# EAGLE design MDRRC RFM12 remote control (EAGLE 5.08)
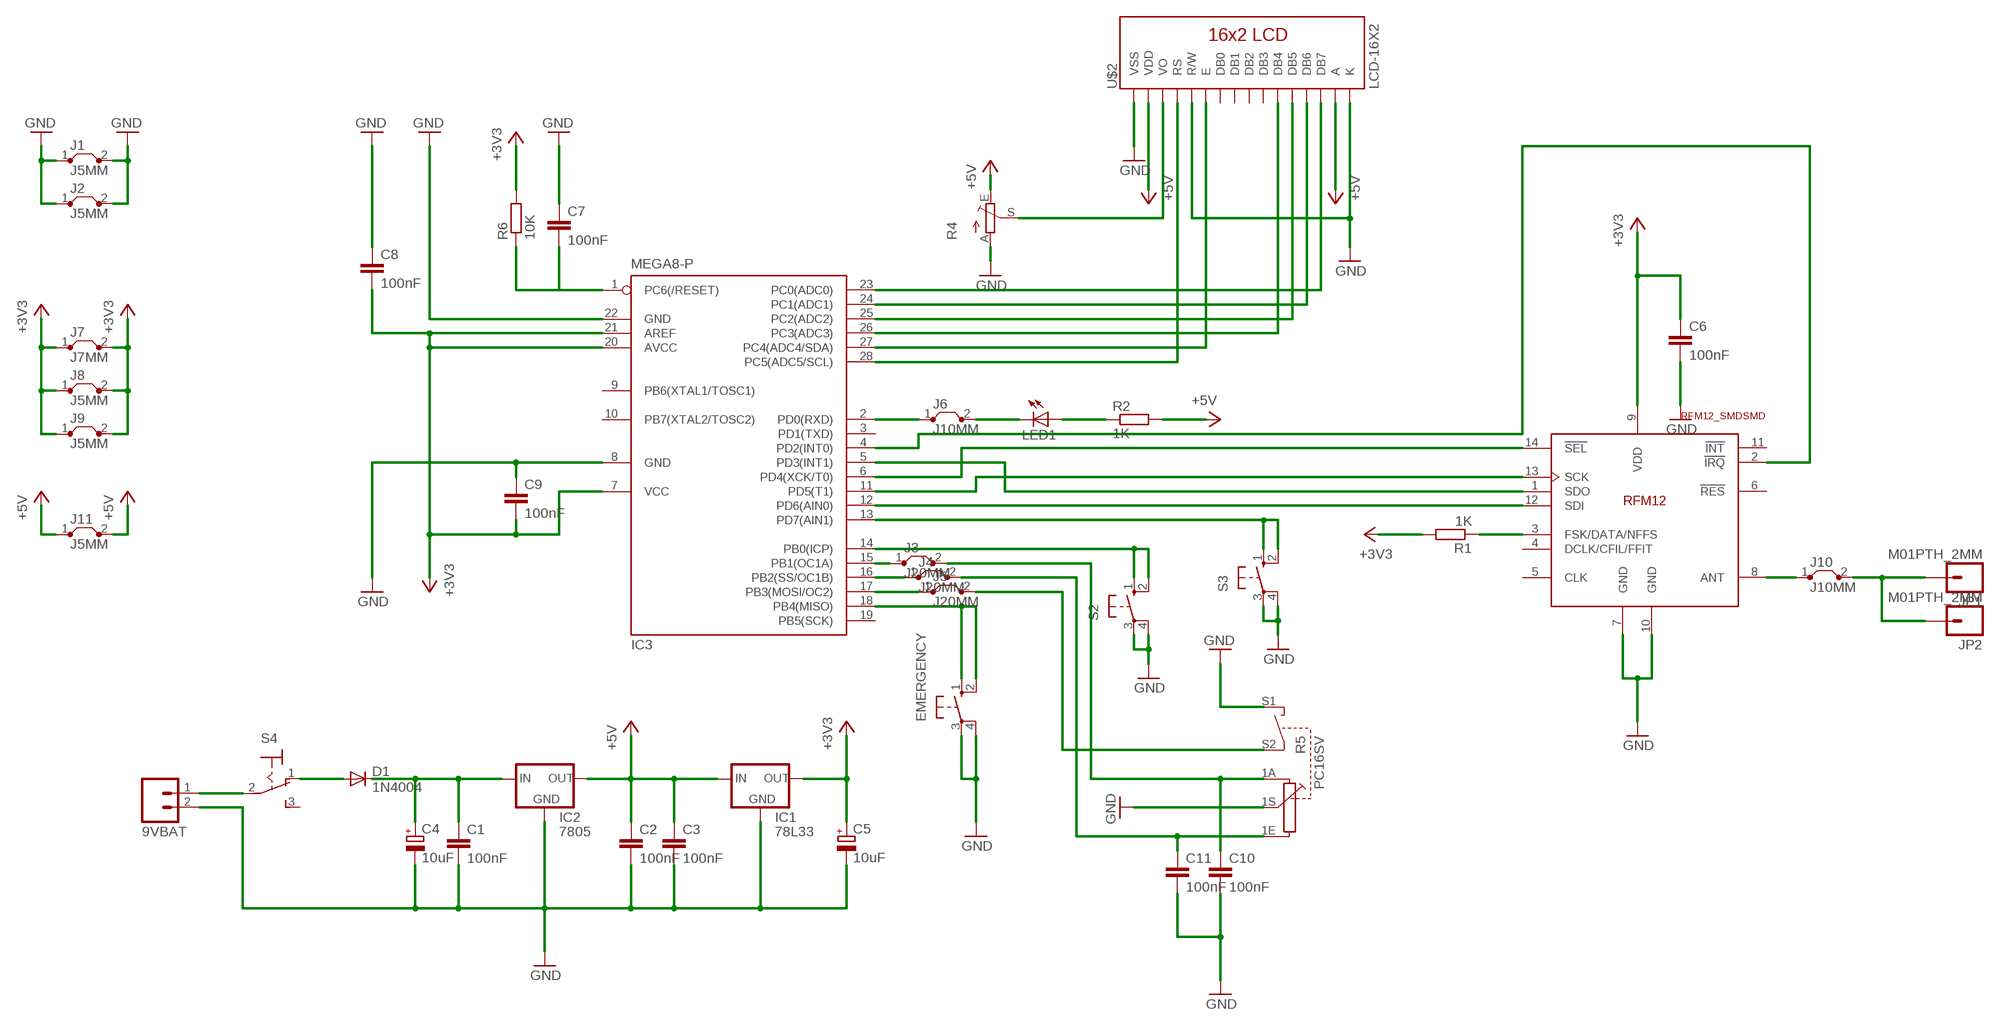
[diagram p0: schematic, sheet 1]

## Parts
9VBAT  M02LOCK_LONGPADS  [1X02_LOCK_LONGPADS]
C1  100nF  C-EU025-025X050  [C025-025X050]
C2  100nF  C-EU025-025X050  [C025-025X050]
C3  100nF  C-EU025-025X050  [C025-025X050]
C4  10uF  CPOL-EUE2.5-6  [E2,5-6]
C5  10uF  CPOL-EUE2.5-6  [E2,5-6]
C6  100nF  C-EU025-025X050  [C025-025X050]
C7  100nF  C-EU025-025X050  [C025-025X050]
C8  100nF  C-EU025-025X050  [C025-025X050]
C9  100nF  C-EU025-025X050  [C025-025X050]
C10  100nF  C-EU025-025X050  [C025-025X050]
C11  100nF  C-EU025-025X050  [C025-025X050]
D1  1N4004  [DO41-10]
EMERGENCY  10-XX  [B3F-10XX]
IC1  78L33  78LXX  [78LXX]
IC2  7805  78XXS  [78XXS]
IC3  MEGA8-P  [DIL28-3]
J1  J5MM  [05]
J2  J5MM  [05]
J3  J20MM  [20]
J4  J20MM  [20]
J5  J20MM  [20]
J6  J10MM  [10]
J7  J7MM  [07]
J8  J5MM  [05]
J9  J5MM  [05]
J10  J10MM  [10]
J11  J5MM  [05]
JP1  M01PTH_2MM  [1X01_2MM]
JP2  M01PTH_2MM  [1X01_2MM]
LED1  LED3MM  [LED3MM]
R1  1K  R-EU_0207/15  [0207/15]
R2  1K  R-EU_0207/10  [0207/10]
R4  TRIM_EU-CA6V  [CA6V]
R5  PC16SV  [PC16SV]
R6  10K  R-EU_0207/15  [0207/15]
S2  10-XX  [B3F-10XX]
S3  10-XX  [B3F-10XX]
S4  M9040P  [M9040P]
U$1  RFM12_SMDSMD  [RFM12]
U$2  LCD-16X2  [LCD-16X2]

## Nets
+3V3: C5.+ C6.1 C8.2 C9.2 IC1.OUT IC3.7(VCC) IC3.20(AVCC) IC3.21(AREF) J7.1 J7.2 J8.1 J8.2 J9.1 J9.2 R1.2 R6.2 U$1.9(VDD)
+5V: C2.1 C3.1 IC1.IN IC2.OUT J11.1 J11.2 R2.2 R4.E U$2.2(VDD) U$2.15(A)
GND: 9VBAT.2 C1.2 C2.2 C3.2 C4.- C5.- C6.2 C7.1 C8.1 C9.1 C10.2 C11.2 EMERGENCY.3(P) EMERGENCY.4(P1) IC1.GND IC2.GND IC3.8(GND) IC3.22(GND) J1.1 J1.2 J2.1 J2.2 R4.A R5.1S R5.S1 S2.3(P) S2.4(P1) S3.3(P) S3.4(P1) U$1.7(GND) U$1.10(GND) U$2.1(VSS) U$2.5(R/W) U$2.16(K)
N$1: D1.A S4.1(O)
N$2: C1.1 C4.+ D1.C IC2.IN
N$3: 9VBAT.1 S4.2(P)
N$4: IC3.2(PD0(RXD)) J6.1
N$5: C7.2 IC3.1(PC6(/RESET)) R6.1
N$6: R4.S U$2.3(VO)
N$7: J5.2 R5.S2
N$8: LED1.A R2.1
N$9: J6.2 LED1.K(C)
N$10: J10.2 JP1.1 JP2.1
N$11: R1.1 U$1.3(FSK/DATA/NFFS)
N$12: IC3.28(PC5(ADC5/SCL)) U$2.4(RS)
N$13: IC3.27(PC4(ADC4/SDA)) U$2.6(E)
N$14: IC3.23(PC0(ADC0)) U$2.14(DB7)
N$15: IC3.24(PC1(ADC1)) U$2.13(DB6)
N$16: IC3.25(PC2(ADC2)) U$2.12(DB5)
N$17: IC3.26(PC3(ADC3)) U$2.11(DB4)
N$18: IC3.12(PD6(AIN0)) U$1.12(SDI)
N$19: IC3.5(PD3(INT1)) U$1.1(SDO)
N$20: IC3.11(PD5(T1)) U$1.13(SCK)
N$21: IC3.6(PD4(XCK/T0)) U$1.14(!SEL)
N$22: IC3.4(PD2(INT0)) U$1.2(!IRQ)
N$23: J10.1 U$1.8(ANT)
N$24: EMERGENCY.1(S) EMERGENCY.2(S1) IC3.18(PB4(MISO))
N$25: IC3.15(PB1(OC1A)) J3.1
N$26: IC3.14(PB0(ICP)) S2.1(S) S2.2(S1)
N$27: IC3.13(PD7(AIN1)) S3.1(S) S3.2(S1)
N$28: IC3.16(PB2(SS/OC1B)) J4.1
N$29: IC3.17(PB3(MOSI/OC2)) J5.1
N$30: C10.1 J3.2 R5.1A
N$31: C11.1 J4.2 R5.1E
Unconnected: IC3.3(PD1(TXD)) IC3.9(PB6(XTAL1/TOSC1)) IC3.10(PB7(XTAL2/TOSC2)) IC3.19(PB5(SCK)) S4.3(S) U$1.4(DCLK/CFIL/FFIT) U$1.5(CLK) U$1.6(!RES) U$1.11(!INT) U$2.7(DB0) U$2.8(DB1) U$2.9(DB2) U$2.10(DB3)

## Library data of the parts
9VBAT = SparkFun:M02: Header 2
C1-C3 C6-C11 = rcl:C-EU: CAPACITOR, European symbol
C4 C5 = resistor:CPOL-EU: POLARIZED CAPACITOR, European symbol
D1 = diode:1N4004: DIODE
EMERGENCY S2 S3 = switch-omron:10-XX: OMRON SWITCH
IC1 = v-reg:78LXX: VOLTAGE REGULATOR
IC2 = v-reg:78XXS: VOLTAGE REGULATOR
IC3 = atmel:MEGA8-P: MICROCONTROLLER 8 Kbytes FLASH, 1 kbytes SRAM, 512 bytes EEPROM, USART, 4-channel 10 bit ADC, 2-channel 8 bit ADC Pin compatible with Atmega48, ATMega88, ATMega168 Source: avr.lbr
J1-J11 = jumper:J: Bridge
JP1 JP2 = SparkFun:M01: Header 1
LED1 = led:LED: LED
R1 R6 = rcl:R-EU_: RESISTOR, European symbol
R2 = resistor:R-EU_: RESISTOR, European symbol
R4 = pot:TRIM_EU-: POTENTIOMETER
R5 = piher:PC16SV: POTENTIOMETER vertical single carbon potentiometer with switch, 16 mm
S4 = switch:M9040P: TOGGLE SWITCH Marquardt
U$1 = rfm_12:RFM12_SMD: RFM12 is a low costing ISM band transceiver module implemented with unique PLL. It works signal ranges from 315/433/868/915MHZ bands, comply with FCC, ETSI regulation. The SPI interface is used to communicate with microcontroller for parameter setting.
U$2 = SparkFun:LCD-16X2

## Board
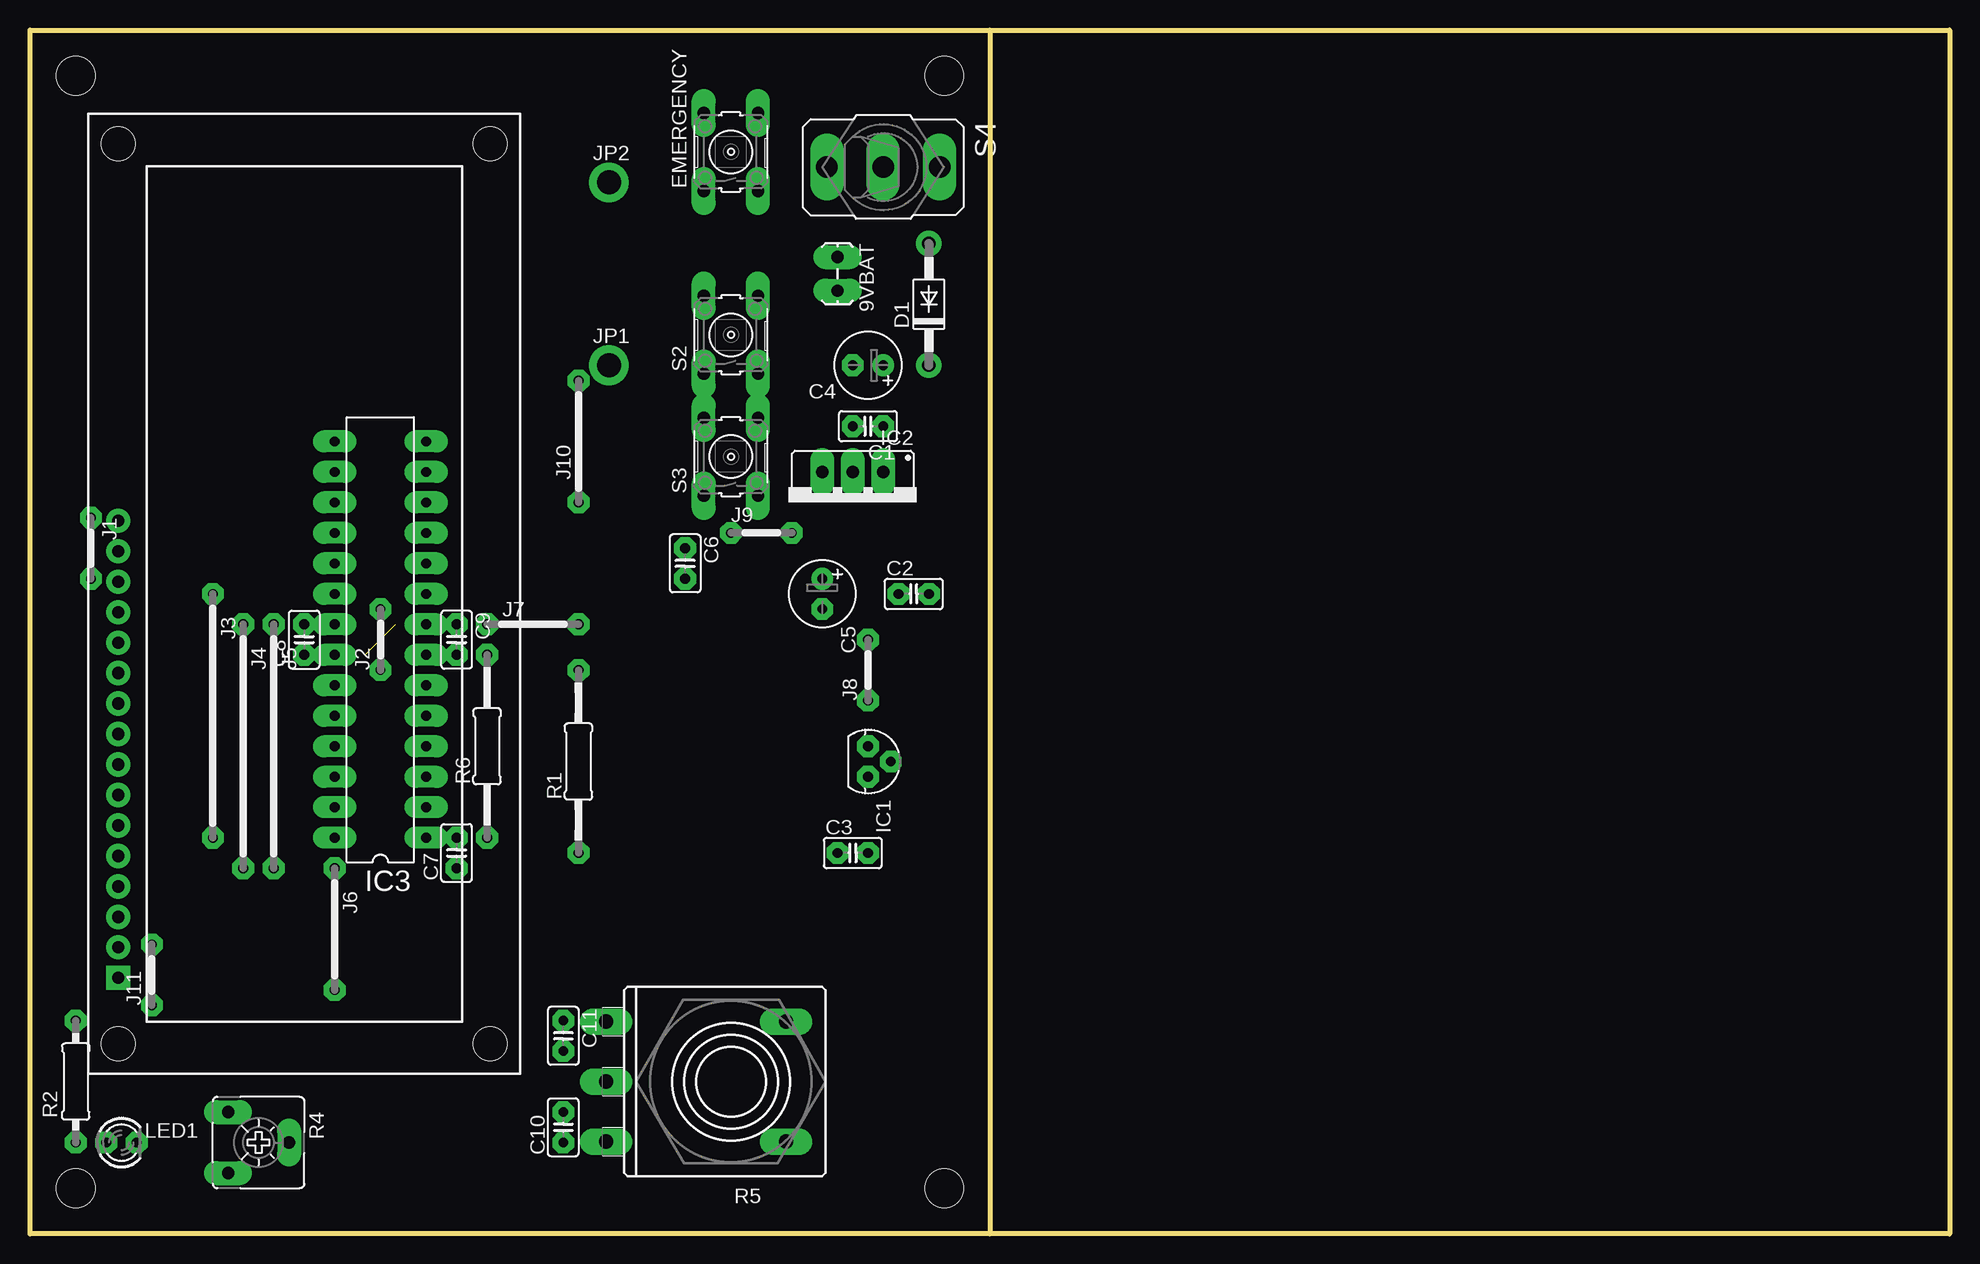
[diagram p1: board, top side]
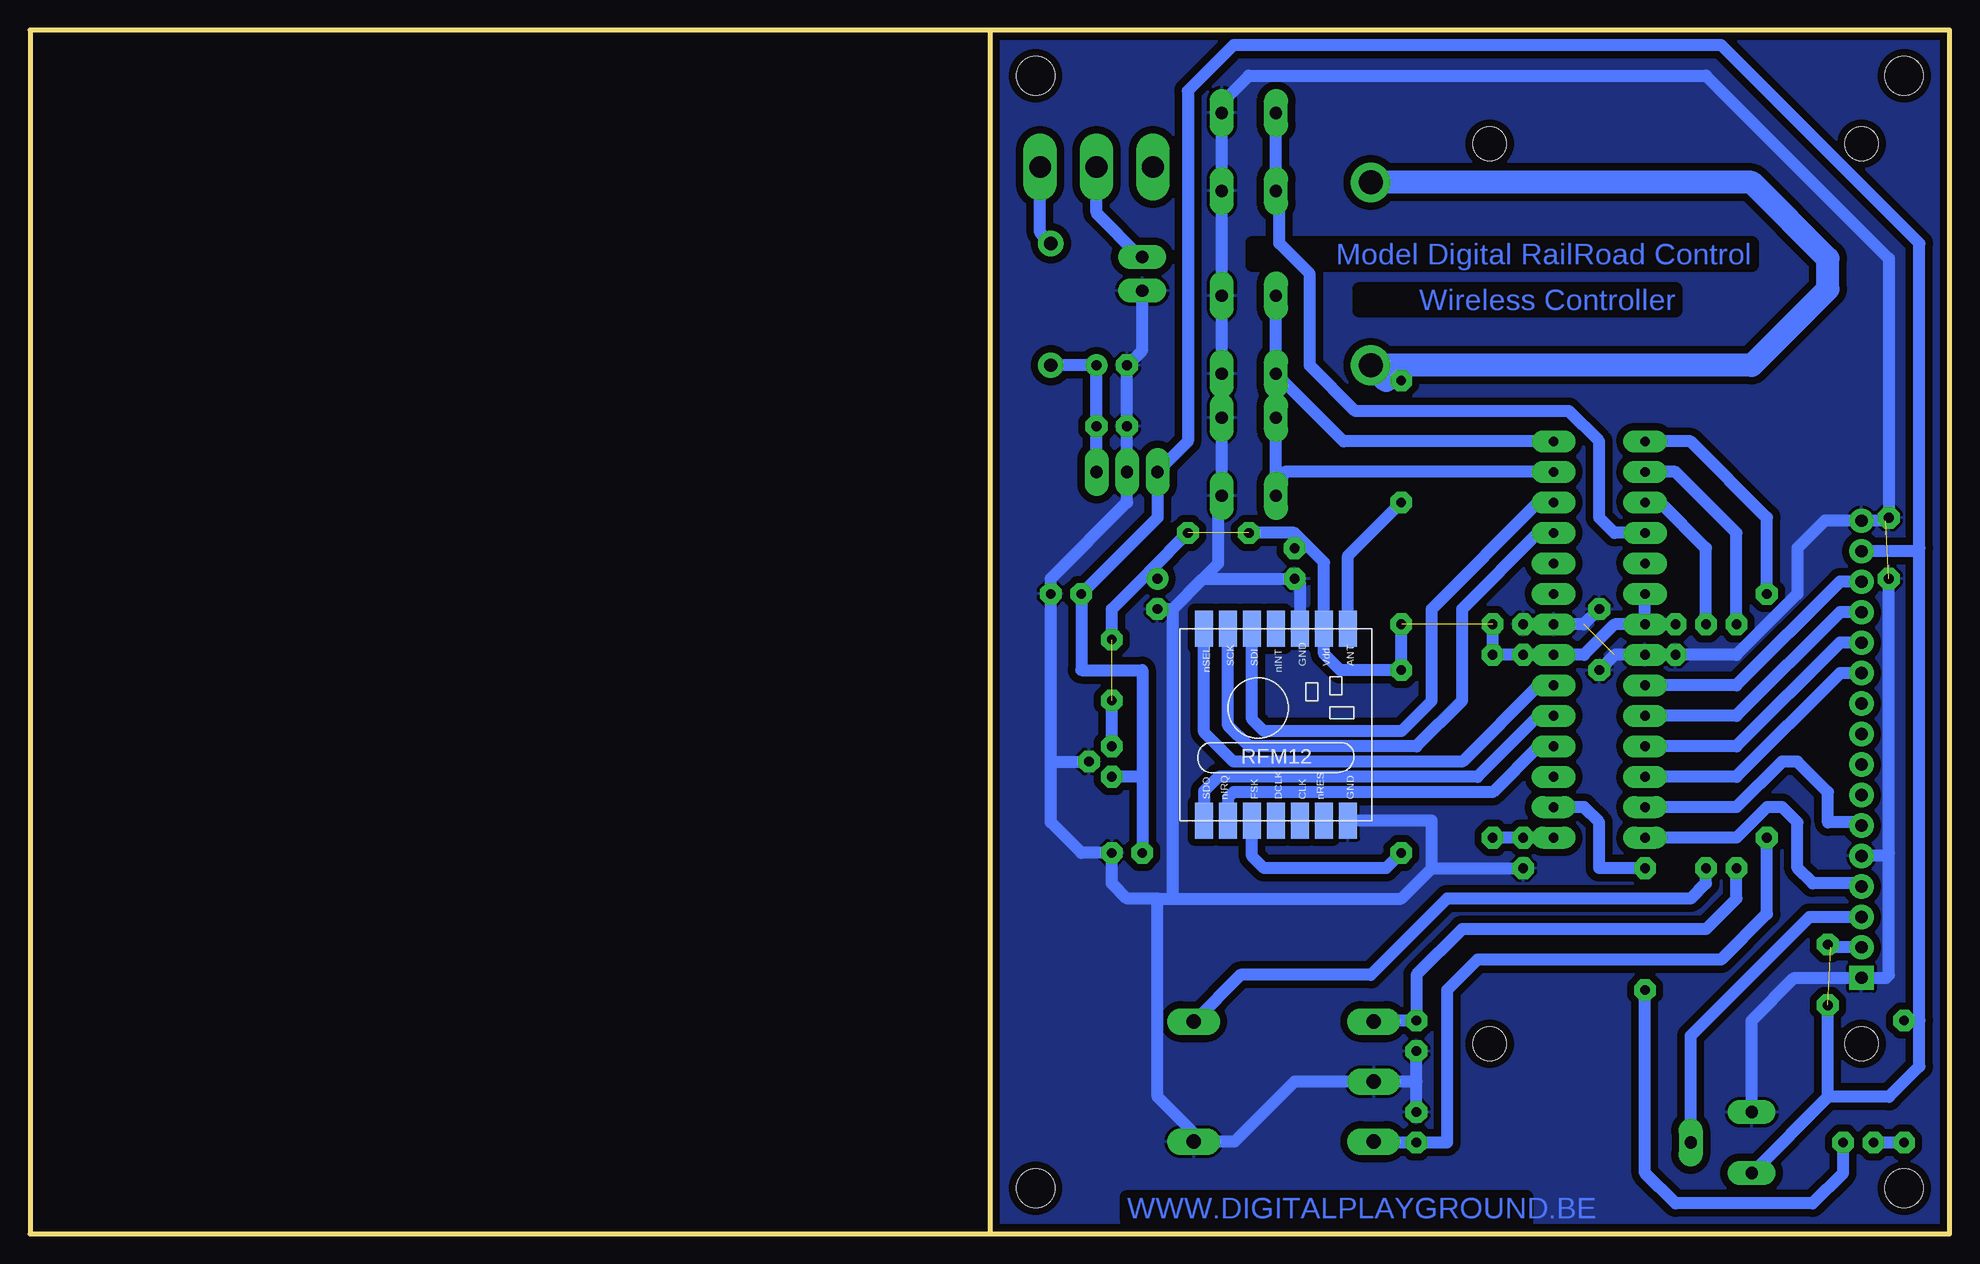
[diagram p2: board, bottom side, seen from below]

Size 160.02 x 100.33 mm. Coordinates in mm from the lower left corner, seen from the top.
Outline: 80.01,100.33 0,100.33 0,0 80.01,0
Outline: 80.01,100.33 160.02,100.33 160.02,0 80.01,0
Outline: 80.01,100.33 80.01,0
Copper layers (1*16): Top 0.8mm / dielectric 1.3mm / Bottom 0.8mm
Design rules "DRC settings smallest": minimum track width 0.8mm, minimum drill 24mil, track to track 0.2mm, track to pad 0.2mm, pad to pad 0.2mm, via to via 0.2mm, smd to smd 8mil, copper to edge 0.3mm, drill to drill 0.3mm, minimum pad ring 0.5mm, minimum via ring 1mm, stop-mask expansion 4mil, vias tented up to drill 0mil, thermal gap 10mil
Holes 3.2 mm at 3.81,96.52 3.81,3.81 76.2,3.81 76.2,96.52

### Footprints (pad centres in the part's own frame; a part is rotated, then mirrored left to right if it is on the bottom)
1X02_LOCK_LONGPADS = drill 1.016 long: 1 -0.127,0; 2 2.667,0
C025-025X050 = drill 0.813 octagon: 1 -1.27,0; 2 1.27,0
E2,5-6 = drill 0.813 pad 1.6 round: + -1.27,0 | drill 0.813 pad 1.6 octagon: - 1.27,0
DO41-10 = drill 1.118 round: A 5.08,0; C -5.08,0
B3F-10XX = drill 1.016 long: 1 -3.251,2.261; 2 3.251,2.261; 3 -3.251,-2.261; 4 3.251,-2.261
78LXX = drill 0.813 octagon: GND 0,1.905; IN 1.27,0; OUT -1.27,0
78XXS = drill 1.016 long: GND 0,-2.54; IN -2.54,-2.54; OUT 2.54,-2.54
DIL28-3 = drill 0.813 long: 1 -16.51,-3.81; 2 -13.97,-3.81; 3 -11.43,-3.81; 4 -8.89,-3.81; 5 -6.35,-3.81; 6 -3.81,-3.81; 7 -1.27,-3.81; 8 1.27,-3.81; 9 3.81,-3.81; 10 6.35,-3.81; 11 8.89,-3.81; 12 11.43,-3.81; 13 13.97,-3.81; 14 16.51,-3.81; 15 16.51,3.81; 16 13.97,3.81; 17 11.43,3.81; 18 8.89,3.81; 19 6.35,3.81; 20 3.81,3.81; 21 1.27,3.81; 22 -1.27,3.81; 23 -3.81,3.81; 24 -6.35,3.81; 25 -8.89,3.81; 26 -11.43,3.81; 27 -13.97,3.81; 28 -16.51,3.81
05 = drill 0.813 pad 1.6 octagon: 1 -2.54,0; 2 2.54,0
20 = drill 0.813 pad 1.6 octagon: 1 -10.16,0; 2 10.16,0
10 = drill 0.813 pad 1.6 octagon: 1 -5.08,0; 2 5.08,0
07 = drill 0.813 pad 1.6 octagon: 1 -3.81,0; 2 3.81,0
1X01_2MM = drill 2 pad 3.302 round: 1 0,0
LED3MM = drill 0.813 octagon: A -1.27,0; K 1.27,0
0207/15 = drill 0.813 octagon: 1 -7.62,0; 2 7.62,0
0207/10 = drill 0.813 octagon: 1 -5.08,0; 2 5.08,0
CA6V = drill 1.016 long: A -2.54,-2.54; E 2.54,-2.54; S 0,2.54
PC16SV = drill 1.2 long: 1A -5,10.4; 1E 5,10.4; 1S 0,10.4; S1 -5,-4.6; S2 5,-4.6
M9040P = drill 1.803 long: 1 0,4.699; 2 0,0; 3 0,-4.699
RFM12 = smd 1.5 x 3: 1 -5,-10; 2 -3,-10; 3 -1,-10; 4 1,-10; 5 3,-10; 6 5,-10; 7 7,-10; 8 7,6; 9 5,6; 10 3,6; 11 1,6; 12 -1,6; 13 -3,6; 14 -5,6
LCD-16X2 = drill 1.016 square: 1 -32,15.5 | drill 1.016 round: 2 -29.46,15.5; 3 -26.92,15.5; 4 -24.38,15.5; 5 -21.84,15.5; 6 -19.3,15.5; 7 -16.76,15.5; 8 -14.22,15.5; 9 -11.68,15.5; 10 -9.14,15.5; 11 -6.6,15.5; 12 -4.06,15.5; 13 -1.52,15.5; 14 1.02,15.5; 15 3.56,15.5; 16 6.1,15.5 | hole 2.8: -37.5,15.5; -37.5,-15.5; 37.5,15.5; 37.5,-15.5

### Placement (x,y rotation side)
9VBAT  67.31,81.28 270 top
C1  69.85,67.31 180 top
C2  73.66,53.34 0 top
C3  68.58,31.75 0 top
C4  69.85,72.39 180 top
C5  66.04,53.34 270 top
C6  54.61,55.88 270 top
C7  35.56,31.75 90 top
C8  22.86,49.53 90 top
C9  35.56,49.53 270 top
C10  44.45,8.89 90 top
C11  44.45,16.51 270 top
D1  74.93,77.47 90 top
EMERGENCY  58.42,90.17 90 top
IC1  69.85,39.37 270 top
IC2  68.58,60.96 180 top
IC3  29.21,49.53 90 top
J1  5.08,57.15 270 top
J2  29.21,49.53 90 top
J3  15.24,43.18 270 top
J4  17.78,40.64 270 top
J5  20.32,40.64 270 top
J6  25.4,25.4 270 top
J7  41.91,50.8 0 top
J8  69.85,46.99 90 top
J9  60.96,58.42 0 top
J10  45.72,66.04 90 top
J11  10.16,21.59 90 top
JP1  48.26,72.39 0 top
JP2  48.26,87.63 0 top
LED1  7.62,7.62 0 top
R1  45.72,39.37 90 top
R2  3.81,12.7 90 top
R4  19.05,7.62 270 top
R5  58.42,12.7 90 top
R6  38.1,40.64 90 top
S2  58.42,74.93 90 top
S3  58.42,64.77 90 top
S4  71.12,88.9 270 top
U$1  57.15,44.45 0 bottom
U$2  22.86,53.34 90 top

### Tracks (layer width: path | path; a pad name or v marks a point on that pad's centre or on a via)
+3V3  (3 unrouted)
  Bottom 1.016: C8.2 IC3.21 | IC3.21 IC3.20 | IC3.21 27.94,50.8 30.48,48.26 IC3.7 C9.2 R6.2 J7.1 | J7.2 R1.2 50.8,46.99 52.15,48.34 U$1.9 52.15,55.96 54.61,58.42 | IC1.OUT J8.1 | J8.2 69.85,52.07 66.67,55.24 | 66.67,55.24 J9.2 | 66.67,55.24 C5.+ | 54.61,58.42 J9.1 | 54.61,58.42 C6.1
+5V  (1 unrouted)
  Bottom 1.016: 2.54,17.78 2.54,13.97 5.08,11.43 10.16,11.43 | 2.54,17.78 2.54,57.15 | 67.31,38.1 67.31,46.99 72.39,46.99 C2.1 66.04,59.69 IC2.OUT 63.5,66.04 63.5,95.25 59.69,99.06 19.05,99.06 2.54,82.55 2.54,57.15 | 67.31,38.1 IC1.IN | 67.31,38.1 C3.1 | U$2.15 2.79,56.9 2.54,57.15 | 7.87,23.88 U$2.2 9.91,23.88 J11.2 | 10.16,11.43 R4.E | 10.16,11.43 J11.1 | 2.54,17.78 R2.2
GND  (2 unrouted)
  Bottom 1.016: J2.2 30.48,50.8 IC3.8 C9.1 | J2.1 27.94,48.26 IC3.22 C8.1 17.78,48.26 12.7,53.34 12.7,57.15 10.41,59.44 U$2.16 5.33,59.44 J1.1 5.08,81.28 20.32,96.52 58.42,96.52 60.68,94.26 S3.3 | C10.2 44.45,12.7 | 44.45,12.7 C11.2 | 44.45,12.7 R5.1S 54.61,12.7 59.61,7.7 R5.S1 63.02,8.41 66.04,11.43 66.04,27.94 | EMERGENCY.4 EMERGENCY.3 S2.4 S2.3 S3.4 S3.3 | U$1.7 43.18,34.45 43.18,30.48 | S3.3 60.96,62.51 60.96,55.88 62.23,54.61 | 64.77,52.07 62.23,54.61 | 64.77,52.07 C5.- | 64.77,27.94 64.77,52.07 | 74.93,39.37 IC1.GND | 74.93,39.37 74.93,34.29 72.39,31.75 C3.2 69.85,29.21 68.58,27.94 66.04,27.94 | 66.04,27.94 64.77,27.94 | 74.93,39.37 C2.2 74.93,54.61 68.58,60.96 IC2.GND C1.2 C4.- 67.31,73.66 9VBAT.2 | 64.77,27.94 45.72,27.94 43.18,30.48 | 5.08,31.75 5.08,21.59 5.33,21.34 U$2.1 12.95,21.34 16.51,17.78 R4.A | U$2.5 5.33,31.5 5.08,31.75 | 5.08,31.75 J1.2 | 43.18,30.48 C7.1 | U$1.10 54.15,54.15 C6.2 62.23,54.61
  pour Bottom (isolate 0.61): 0,100.33 80.01,100.33 80.01,0 0,0
N$1
  Bottom 1.016: S4.1 75.82,83.44 D1.A
N$2
  Bottom 1.016: IC2.IN C1.1 C4.+ D1.C
N$3
  Bottom 1.016: 9VBAT.1 67.44,81.41 71.12,85.09 S4.2
N$4
  Bottom 1.016: IC3.2 30.48,35.56 29.21,34.29 29.21,30.48 J6.1
N$5
  Bottom 1.016: IC3.1 C7.2 R6.1
N$6
  Bottom 1.016: U$2.3 11.68,26.42 21.59,16.51 R4.S
N$7
  Bottom 1.016: J5.2 20.32,29.21 21.59,27.94 41.91,27.94 48.26,21.59 59.13,21.59 R5.S2
N$8
  Bottom 1.016: R2.1 LED1.A
N$9
  Bottom 1.016: J6.2 25.4,5.08 22.86,2.54 11.43,2.54 8.89,5.08 LED1.K
N$10
  Bottom 1.016: 46.99,71.12 J10.2
  Bottom 1.93: 46.99,71.12 JP1.1 16.51,72.39 10.16,78.74 10.16,81.28 16.51,87.63 JP2.1
N$11
  Bottom 1.016: U$1.3 58.15,31.48 57.15,30.48 46.99,30.48 R1.1
N$12
  Bottom 1.016: IC3.28 17.78,33.02 15.24,35.56 13.97,35.56 12.7,34.29 12.7,30.48 11.43,29.21 7.61,29.21 U$2.4
N$13
  Bottom 1.016: IC3.27 17.78,35.56 13.97,39.37 12.7,39.37 10.16,36.83 10.16,34.29 7.61,34.29 U$2.6
N$14
  Bottom 1.016: U$2.14 9.14,54.36 17.78,45.72 IC3.23
N$15
  Bottom 1.016: U$2.13 9.14,51.82 17.78,43.18 IC3.24
N$16
  Bottom 1.016: U$2.12 9.14,49.28 17.78,40.64 IC3.25
N$17
  Bottom 1.016: U$2.11 9.14,46.74 17.78,38.1 IC3.26
N$18
  Bottom 1.016: U$1.12 58.15,42.91 57.15,41.91 45.72,41.91 43.18,44.45 43.18,52.07 34.29,60.96 IC3.12
N$19
  Bottom 1.016: U$1.1 62.15,36.91 60.96,38.1 39.37,38.1 34.29,43.18 IC3.5
N$20
  Bottom 1.016: U$1.13 60.15,42.37 58.42,40.64 44.45,40.64 40.64,44.45 40.64,52.07 34.29,58.42 IC3.11
N$21
  Bottom 1.016: U$1.14 62.15,41.83 59.69,39.37 40.64,39.37 34.29,45.72 IC3.6
N$22
  Bottom 1.016: IC3.4 34.29,40.64 38.1,36.83 59.69,36.83 60.15,36.37 U$1.2
N$23
  Bottom 1.016: U$1.8 50.15,56.53 J10.1
N$24
  Bottom 1.016: EMERGENCY.2 EMERGENCY.1 55.88,86.64 55.88,82.55 53.34,80.01 53.34,72.39 49.53,68.58 31.75,68.58 29.21,66.04 29.21,59.69 27.94,58.42 IC3.18
N$25
  Bottom 1.016: IC3.15 21.59,66.04 15.24,59.69 J3.1
N$26
  Bottom 1.016: S2.2 S2.1 50.52,66.04 IC3.14
N$27
  Bottom 1.016: S3.2 S3.1 55.45,63.5 IC3.13
N$28
  Bottom 1.016: IC3.16 22.86,63.5 17.78,58.42 J4.1
N$29
  Bottom 1.016: IC3.17 24.13,60.96 20.32,57.15 J5.1
N$30
  Bottom 1.016: R5.1A 47.94,7.62 C10.1 41.91,7.62 41.91,20.32 39.37,22.86 19.05,22.86 15.24,26.67 J3.2
N$31
  Bottom 1.016: R5.1E 47.94,17.78 C11.1 44.45,21.59 40.64,25.4 20.32,25.4 17.78,27.94 J4.2

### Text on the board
Bottom: Model Digital RailRoad Control | Wireless Controller | WWW.DIGITALPLAYGROUND.BE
